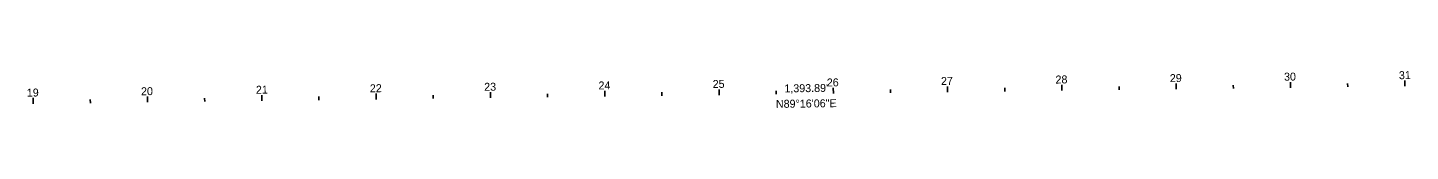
# Model space of a CAD drawing. Extents: x 1805326 to 1810276, y 297762 to 303660.
# Drawn here: x 1806559 to 1807769, y 298342 to 298374 of the extents above; entities that cross this region are included whole.
import ezdxf

# ---------------------------------------------------------------- set-up
doc = ezdxf.new("R2010")
doc.units = 0
for name, color, linetype in [('GE_P_Alignment_100_Bearings', 7, 'Continuous'), ('GE_P_Alignment_100_Distances', 7, 'Continuous'), ('GE_P_Alignment_100_Stations', 7, 'Continuous')]:
    doc.layers.add(name, color=color, linetype=linetype)

msp = doc.modelspace()

# ---------------------------------------------------------------- linework, layer by layer
at = {"layer": 'GE_P_Alignment_100_Stations'}
for p, q in [((1807764.2, 298361), (1807764.1, 298366)), ((1806864.2, 298349.5), (1806864.2, 298354.5)), ((1806964.2, 298350.8), (1806964.2, 298355.8)), ((1807014.2, 298351.4), (1807014.2, 298354.4)), ((1807064.2, 298352.1), (1807064.2, 298357.1)), ((1807114.2, 298352.7), (1807114.2, 298355.7)), ((1807164.2, 298353.3), (1807164.2, 298358.3)), ((1807214.2, 298354), (1807214.2, 298357)), ((1807264.2, 298354.6), (1807264.1, 298359.6)), ((1807314.2, 298355.3), (1807314.2, 298358.3)), ((1807364.2, 298355.9), (1807364.1, 298360.9)), ((1807414.2, 298356.5), (1807414.2, 298359.5)), ((1807464.2, 298357.2), (1807464.1, 298362.2)), ((1807514.2, 298357.8), (1807514.2, 298360.8)), ((1807564.2, 298358.4), (1807564.1, 298363.4)), ((1807614.2, 298359.1), (1807614.1, 298362.1)), ((1807664.2, 298359.7), (1807664.1, 298364.7)), ((1807714.2, 298360.4), (1807714.1, 298363.4)), ((1806564.3, 298345.7), (1806564.2, 298350.7)), ((1806614.3, 298346.3), (1806614.2, 298349.3)), ((1806664.3, 298347), (1806664.2, 298352)), ((1806714.3, 298347.6), (1806714.2, 298350.6)), ((1806764.3, 298348.2), (1806764.2, 298353.2)), ((1806814.2, 298348.9), (1806814.2, 298351.9)), ((1806914.2, 298350.2), (1806914.2, 298353.1))]:
    msp.add_line(p, q, dxfattribs=at)

# ---------------------------------------------------------------- texts
at = {"layer": 'GE_P_Alignment_100_Bearings'}
msp.add_text('N89°16\'06"E', height=7, rotation=0.7316, dxfattribs=at).set_placement((1807214, 298342))
at = {"layer": 'GE_P_Alignment_100_Distances'}
msp.add_text("1,393.89'", height=7, rotation=0.7316, dxfattribs=at).set_placement((1807221.4, 298355.6))
at = {"layer": 'GE_P_Alignment_100_Stations'}
for s, p in [('25', (1807158.7, 298359.5)), ('26', (1807258.5, 298360.8)), ('27', (1807358.4, 298362.1)), ('28', (1807458.6, 298363.4)), ('29', (1807558.6, 298364.6)), ('30', (1807658.5, 298365.9)), ('31', (1807759, 298367.2)), ('19', (1806558.7, 298351.9)), ('20', (1806658.6, 298353.1)), ('21', (1806759.1, 298354.4)), ('22', (1806858.8, 298355.7)), ('23', (1806958.8, 298357)), ('24', (1807058.8, 298358.2))]:
    msp.add_text(s, height=7, rotation=0.7316, dxfattribs=at).set_placement(p)

doc.saveas('drawing.dxf')
